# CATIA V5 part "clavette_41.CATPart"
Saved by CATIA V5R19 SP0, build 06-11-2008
Part number: clavette_41
Bounding box of the stored display mesh (mm): x -7.5 to 7.5, y -32.49 to 32.49, z -5 to 5
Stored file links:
  C:\Users\Thinkmotion2\Desktop\Pack 2\CFAO_2010\abaussand\CFAO_abaussand_Catia_V5R20\clavette_41.CATPart
  C:\Users\Thinkmotion2\Desktop\Pack 2\CFAO_2010\abaussand\CFAO_abaussand_Catia_V5R20\abaussand_2.CATProduct
  C:\Users\Thinkmotion2\Desktop\Pack 2\CFAO_2010\abaussand\CFAO_abaussand_Catia_V5R20\support_17.CATPart
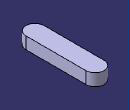
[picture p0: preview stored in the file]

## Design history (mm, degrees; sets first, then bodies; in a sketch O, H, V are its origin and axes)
Body1 (main body)
  Sketch1 on xy-plane, origin (0, 0, 0), H (1, 0, 0), V (0, 1, 0)
    line L1 (-7.5, 25) -> (-7.5, -25)
    arc A1 centre (0, -25) radius 7.5 from (-7.5, -25) to (7.5, -25) ccw
    point P3 (0, -25)
    line L2 (7.5, -25) -> (7.5, 25)
    arc A2 centre (0, 25) radius 7.5 from (7.5, 25) to (-7.5, 25) ccw
    length L2 = 50
    distance P3 H = 25
    distance L2 L1 = 15
    distance L1 V = 7.5
    vertical: L1 V
    tangency: A1 L1, L2 A1, A2 L1, A2 L2
  Pad1: profile Sketch1, direction (0, 0, 1), length 5, mirrored extent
